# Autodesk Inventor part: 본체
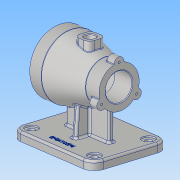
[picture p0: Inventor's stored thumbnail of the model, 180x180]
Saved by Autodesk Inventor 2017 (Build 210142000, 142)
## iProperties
Part Number: 본체
Material: 알루미늄 6061
Document SubType Name: Modeling
Designer: user
Density: 2.7 g/cm^3
Appearance: 알루미늄 - 평지
Mass: 1225.27 g
Surface Area: 902.535 cm^2
Volume: 453.804 cm^3
Author: user
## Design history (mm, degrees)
sketch "스케치1"
  geometry: L1 (70, 55)-(-70, 55); L2 (-70, 55)-(-70, -55); L3 (-70, -55)-(70, -55); L4 (70, -55)-(70, 55); L5 (70, 55)-(-70, -55); L6 (-70, 55)-(70, -55); 1 further point
  constraints: 12 end point, 2 midpoint, 2 parallel, 1 horizontal, 1 perpendicular
  dimensions: "d0" = 140 distance of L2.end L3.end; "d1" = 110 distance of L3.end L1.start
extrude "돌출1" new body sketch "스케치1" distance "d2" = 12; taper "d3" = 0 deg
sketch "스케치2"
  geometry: L1 (-50, 82)-(50, 82); L2 (-70, 0)-(70, 0) reference; L3 (-50, 82)-(-50, 127); L4 (-50, 127)-(-30, 127); L5 (-30, 127)-(27, 111); L6 (27, 111)-(50, 111); L7 (50, 82)-(50, 111); 3 further points
  constraints: 12 end point, 2 midpoint, 2 vertical, 1 parallel, 1 perpendicular, 1 vertical alignment
  dimensions: "d4" = 82 distance between parallel lines of L2 L1; "d7" = 90 diameter of L4 L1; "d8" = 20 distance of L3.end L4.end; "d10" = 23 distance of L5.end L6.end; "d11" = 100 distance of L1.start L1.end; "d12" = 58 diameter of L6 L1
revolve "회전1" sketch "스케치2" stored, may be unused: angle "d13" = 90 deg
sketch "스케치3"
  geometry: L1 (-37, -4)-(37, -4); L2 (37, -4)-(37, 4); L3 (37, 4)-(-37, 4); L4 (-37, 4)-(-37, -4); L5 (-37, -4)-(37, 4); L6 (37, -4)-(-37, 4); L7 (-4, -24)-(4, -24); L8 (4, -24)-(4, 24); L9 (4, 24)-(-4, 24); L10 (-4, 24)-(-4, -24); L11 (-4, -24)-(4, 24); L12 (4, -24)-(-4, 24); 1 further point
  constraints: 24 end point, 4 midpoint, 4 parallel, 2 horizontal, 2 perpendicular
  dimensions: "d14" = 74 distance of L2.end L3.end; "d16" = 8 distance of L1.end L2.end; "d17" = 8 distance of L8.end L9.end; "d112" = 24 distance from line of L9 point (0, 0)
extrude "돌출2" join sketch "스케치3" stored distance "d19" = 12; taper "d20" = 0 deg
sketch "스케치4"
  geometry: L1 (-50, 37)-(-50, 127) reference; L2 (50, 53)-(50, 111) reference; L3 (50, 82)-(-50, 82); L4 (-50, 82)-(-50, 113); L5 (-50, 113)-(-27, 113); L6 (-27, 113)-(-27, 107); L7 (-27, 107)-(20, 107); L8 (20, 107)-(20, 101); L9 (20, 101)-(50, 101); L10 (50, 82)-(50, 101); 1 further point
  constraints: 16 end point, 4 perpendicular, 2 midpoint, 2 point on line, 1 collinear, 1 horizontal
  dimensions: "d22" = 62 diameter of L5 L3; "d23" = 23 distance of L4.end L5.end; "d24" = 47 distance of L6.end L7.end; "d25" = 38 diameter of L9 L3; "d26" = 50 diameter of L7 L3
node "작업 평면2"
sketch "스케치7"
  geometry: L1 (-12.5, -12.5)-(12.5, -12.5); L2 (12.5, -12.5)-(12.5, 12.5); L3 (12.5, 12.5)-(-12.5, 12.5); L4 (-12.5, 12.5)-(-12.5, -12.5); L5 (-12.5, -12.5)-(12.5, 12.5); L6 (12.5, -12.5)-(-12.5, 12.5); 1 further point
  constraints: 12 end point, 2 midpoint, 2 parallel, 1 horizontal, 1 perpendicular
  dimensions: "d34" = 25 distance of L2.end L3.end; "d35" = 25 distance of L1.end L2.end
extrude "돌출3" join sketch "스케치7" stored distance "d36" = 12; taper "d37" = 0 deg
revolve "회전3" stored, may be unused: angle "d38" = 90 deg
sketch "스케치8"
  geometry: C1 r 7.5 at (0, 0); 1 further point
  constraints: 1 centre point, 1 coincident
  dimensions: "d39" = 15 diameter of C1
extrude "돌출4" cut sketch "스케치8" distance "d40" = 30; taper "d41" = 0 deg
sketch "스케치9"
  geometry: L1 (70, 55)-(-70, 55) reference; L2 (-70, 55)-(-70, -55) reference; L3 (54, 39)-(-54, 39); L4 (-54, 39)-(-54, -39); L5 (-54, -39)-(54, -39); L6 (54, -39)-(54, 39); L7 (54, 39)-(-54, -39); L8 (-54, 39)-(54, -39); C1 r 9 at (-54, 39); C2 r 9 at (54, 39); C3 r 9 at (54, -39); C4 r 9 at (-54, -39); 1 further point
  constraints: 12 end point, 4 centre point, 4 coincident, 2 midpoint, 2 parallel, 1 horizontal, 1 perpendicular
  dimensions: "d42" = 16 distance between parallel lines of L1 L3; "d43" = 16 distance between parallel lines of L2 L4; "d44" = 18 diameter of C1; "d46" = 18 diameter of C2; "d47" = 18 diameter of C3; "d48" = 18 diameter of C4
extrude "돌출5" cut sketch "스케치9" distance "d49" = 2; taper "d50" = 0 deg
sketch "스케치10"
  geometry: L1 (-16, 94)-(-16, -16) reference; L2 (124, 94)-(-16, 94) reference; L3 (124, -16)-(124, 94) reference; C1 r 9 at (0, 0) reference; C2 r 4.5 at (0, 0); C3 r 4.5 at (0, 78); C4 r 4.5 at (108, 78); C5 r 4.5 at (108, 0); 1 further point
  constraints: 4 centre point, 1 coincident
  dimensions: "d51" = 9 diameter of C2; "d52" = 9 diameter of C3; "d53" = 78 distance of C1.centre C3.centre; "d54" = 16 distance from line of C3.centre L1; "d55" = 9 diameter of C4; "d56" = 16 distance from line of L2 C4.centre; "d57" = 108 distance of C3.centre C4.centre; "d58" = 9 diameter of C5; "d59" = 78 distance of C4.centre C5.centre; "d60" = 16 distance from line of L3 C5.centre
extrude "돌출6" cut sketch "스케치10" stored distance "d61" = 2; taper "d62" = 0 deg
sketch "스케치11" dims "d63" = 80
  geometry: L1 (0, 0)-(-34.641, 20); L2 (0, 0)-(40, 0); C1 r 45 at (0, 0) reference; 7 further points
  constraints: 4 end point, 2 coincident, 1 equal length, 1 horizontal, 10 other
  dimensions: "d64" = 150 deg angle of L2 L1; "d68" = 360 deg dimension on L1.start point (-34.641, 20) (derived)
hole "구멍1" sketch "스케치11" at (-34.641, 20), (-34.641, -20), (0, -40), (34.641, -20), (34.641, 20), (0, 40) diameter "d70" = 3.242; stored, may be unused: countersink angle "d74" = 90 deg, drill point angle "d76" = 118 deg; dims "d71" = 9, "d72" = 4, "d73" = 2, "d75" = 11
sketch "스케치12"
  geometry: L1 (-24, -70)-(-24, -26.099) reference; C1 r 7 at (0, 29); C2 r 7 at (-25.115, -14.5); C3 r 7 at (25.115, -14.5); 3 further points
  constraints: 3 centre point, 1 vertical alignment, 8 other
  dimensions: "d81" = 14 diameter of C1; "d84" = 360 deg dimension on point (0, 0) C1.centre (derived); "d86" = 24 distance from line of C1.centre L1
extrude "돌출7" join sketch "스케치12" distance "d87" = 15; taper "d88" = 0 deg
sketch "스케치13"
  geometry: A1 r 7 centre (0, 0) between (6.949, -0.845) and (-6.949, -0.845) reference; A2 r 7 centre (-25.115, -43.5) between (-27.858, -37.06) and (-20.909, -49.095) reference; A3 r 7 centre (25.115, -43.5) between (20.909, -49.095) and (27.858, -37.06) reference; 4 further points
  constraints: 3 coincident
hole "구멍2" sketch "스케치13" at (0, 0), (-25.115, -43.5), (25.115, -43.5) diameter "d90" = 3.242; stored, may be unused: countersink angle "d94" = 90 deg, drill point angle "d96" = 118 deg; dims "d91" = 9, "d92" = 4, "d93" = 2, "d95" = 11
feature "면 기울기1" dims angle "d97" = 5 deg
node "작업 평면4"
sketch "스케치14"
  geometry: L1 (-70, -55)-(70, -55) reference; 2 further points
  constraints: 1 vertical alignment, 1 other
  dimensions: "d99" = 15 distance from line of L1 point (0, -40)
feature "엠보싱1" sketch "스케치14" dims "d0" = 140, "d1" = 110, "d100" = 0.5, "d101" = 0
fillet "모깎기1" dims "d102" = 16
fillet "모깎기3" dims "d104" = 3
fillet "모깎기4" dims "d105" = 1
fillet "모깎기5" dims "d106" = 3
chamfer "모따기1" distance "d107" = 1; stored, may be unused: second distance "d108" = 2, angle "d109" = 45 deg
fillet "모깎기6" dims "d110" = 8
fillet "모깎기7" dims "d111" = 1
node "솔리드1"
other parameters: "d33" = 115
